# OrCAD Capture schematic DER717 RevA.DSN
size Custom; title: DER 717; rev: A
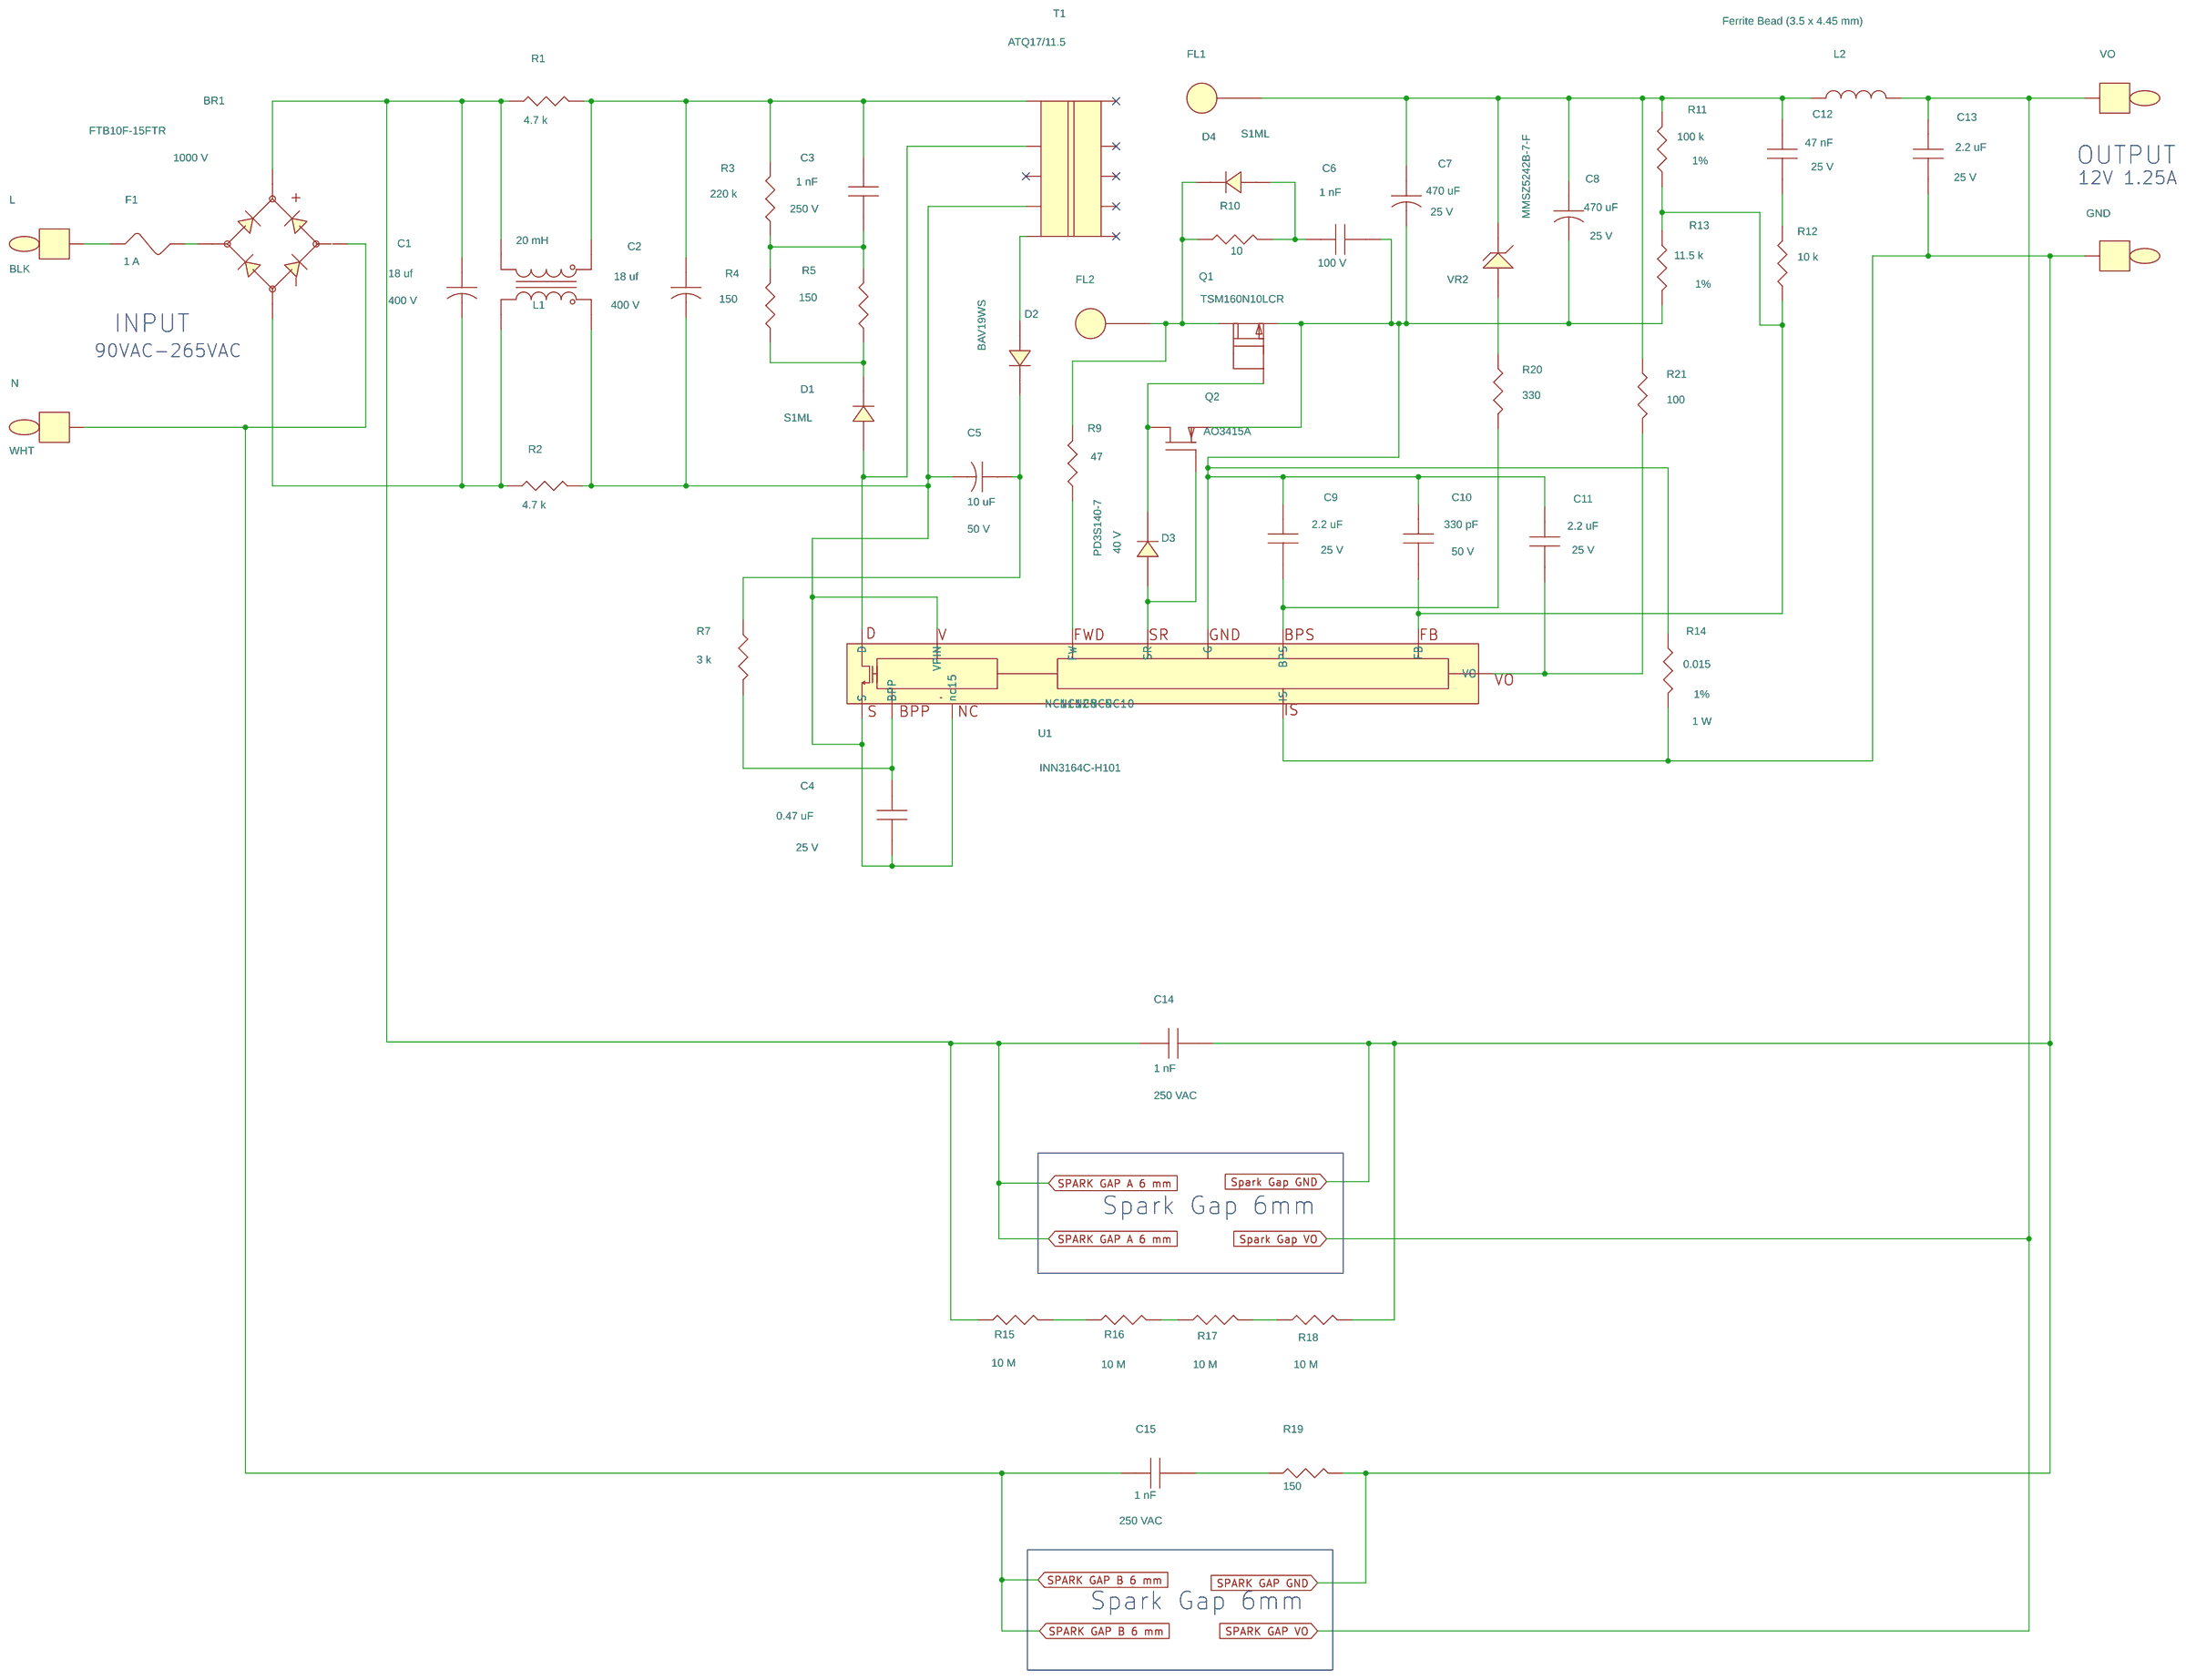
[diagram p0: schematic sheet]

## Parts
BR1  FTB10F-15FTR  [pismd_4SMD]
C1  18 uf  [pipolcapcyld400ls200040]
C2  18 uf  [pipolcapcyld400ls200040]
C3  1 nF  [pismc0805]
C4  0.47 uF  [pismc0805]
C5  10 uF  [pipolcap4p0x11p0xls1p5d030]
C6  1 nF  [pismc0603]
C7  470 uF  [pipolcapcyld400ls200040]
C8  470 uF  [pipolcapcyld400ls200040]
C9  2.2 uF  [pismc0805]
C10  330 pF  [pismc0603]
C11  2.2 uF  [pismc0805]
C12  47 nF  [pismc0603]
C13  2.2 uF  [pismc0805]
C14  1 nF  [pinpycaprad540x290ls400040]
C15  1 nF  [pinpycaprad540x290ls400040]
D1  S1ML  [pi_sm_sod-123_12]
D2  BAV19WS  [pismsod323]
D3  PD3S140-7  [pismd_powerdi323]
D4  S1ML  [pi_sm_sod-123_12]
F1  1 A  [pi_rst_microfuse]
FL1  Hole_50mils  [pi_hole_50mil]
FL2  Hole_50mils  [pi_hole_50mil]
GND  BLK  [pitpkeystone100x100]
L  BLK  [pitpkeystone125x125]
L1  20 mH  [pi_ind_4p_590x295ls394x177d060]
L2  Ferrite Bead (3.5 x 4.45 mm)  [pi12wresd180ls675d040]
N  WHT  [pitpkeystone125x125]
Q1  TSM160N10LCR  [pismpqfn5x6b]
Q2  AO3415A  [pismsot23123_1]
R1  4.7 k  [pismr0805]
R2  4.7 k  [pismr0805]
R3  220 k  [pismr1206]
R4  150  [pismr1206]
R5  150  [pismr1206]
R7  3 k  [pismr0805]
R9  47  [pismr0603]
R10  10  [pismr0805]
R11  100 k  [pismr0603]
R12  10 k  [pismr0603]
R13  11.5 k  [pismr0603]
R14  0.015  [pismr1206]
R15  10 M  [pismr1206]
R16  10 M  [pismr1206]
R17  10 M  [pismr1206]
R18  10 M  [pismr1206]
R19  150  [pismr1206]
R20  330  [pismr0603]
R21  100  [pismr0805]
T1  ATQ17/11.5  [pi_bobbin_ATQ17_H_10P]
U1  INN3164C-H101  [pi_ic_insop_24d]
VO  RED  [pitpkeystone100x100]
VR2  MMSZ5242B-7-F  [pi_sm_sod-123_12]

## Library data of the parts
BR1 = DIODE_BRIDGE_+-~~: Disp_Voltage: 1000 V; Part Number: 15-01264-00
C1 C2 = CAP_POL: ALT_SYMBOLS: pipolcapclyd395x630ls200030h; Disp_Voltage: 400 V; FPLIST: pipolcapcyld400ls200040,pipolcapclyd395x630ls200030h; Part Number: 20-09063-00; Voltage: 400 V
C3 = CAP_NP: Disp_Voltage: 250 V; Part Number: 20-00736-00; Voltage: 250 V
C4 = CAP_NP: Disp_Voltage: 25 V; Part Number: 20-09182-00; Voltage: 25 V
C5 = CAP_POL: Disp_Voltage: 50 V; Part Number: 20-09040-00; Voltage: 50 V
C6 = CAP_NP: Disp_Voltage: 100 V; Part Number: 20-00712-00; Voltage: 100 V
C7 C8 = CAP_POL: ALT_SYMBOLS: pipolcapclyd395x630ls200030h; Disp_Voltage: 25 V; FPLIST: pipolcapcyld400ls200040,pipolcapclyd395x630ls200030h; Part Number: 20-00032-00; Voltage: 25 V
C9 C11 C13 = CAP_NP: Disp_Voltage: 25 V; Part Number: 20-08603-00; Voltage: 25 V
C10 = CAP_NP: ALT_SYMBOLS: pismc0603_1; Disp_Voltage: 50 V; FPLIST: pismc0603,pismc0603_1; Part Number: 20-09235-00; Voltage: 50 V
C12 = CAP_NP: Disp_Voltage: 25 V; Part Number: 20-08756-00; Voltage: 25 V
C14 C15 = CAP_NP: ALT_SYMBOLS: pinpycaprad540x290ls400040h,pinpycaprad500x220ls400040; Disp_Voltage: 250 VAC; FPLIST: pinpycaprad540x290ls400040,pinpycaprad540x290ls400040h,pinpycaprad500x220ls400040; Part Number: 20-00375-00; Voltage: 250 VAC
D1 D4 = DIODE: Part Number: 15-01027-00
D2 = DIODE: Part Number: 15-00658-00
D3 = DIODE: Disp_Voltage: 40 V; Part Number: 15-01025-00
F1 = FUSE: ALT_SYMBOLS: pirstmicrofusehoz; FPLIST: pi_rst_microfuse,pirstmicrofusehoz; Part Number: 40-00053-00
FL1 FL2 = FlyingLead: Part Number: 35-00283-00
GND = TESTPOINT: Part Number: 35-00079-00
L = TESTPOINT: Part Number: 35-00042-00
L1 = INDUCTOR_4P_revD: Part Number: 30-00458-00
L2 = INDUCTOR: ALT_SYMBOLS: pi12wvresd180ls150d040,pi12wvresd180ls200d040,pi12wvresd180ls250d040; FPLIST: pi12wresd180ls675d040,pi12wvresd180ls150d040,pi12wvresd180ls200d040,pi12wvresd180ls250d040; Part Number: 30-00143-00
N = TESTPOINT: Part Number: 35-00044-00
Q1 = FET_N_SGD_123_4_5678: Part Number: 50-00280-00
Q2 = FET_P_GSD: Part Number: 50-00292-00
R1 R2 = R: Part Number: 05-01535-00
R3 = R: Part Number: 05-01408-00
R4 R5 R19 = R: ALT_SYMBOLS: pismr1206_1; FPLIST: pismr1206,pismr1206_1; Part Number: 05-01332-00
R7 = R: Part Number: 05-01530-00
R9 = R: ALT_SYMBOLS: pismr0603_1; FPLIST: pismr0603,pismr0603_1; Part Number: 05-01656-00
R10 = R: Part Number: 05-01471-00
R11 = R: Disp_Tol: 1%; Part Number: 05-01174-00
R12 = R: Part Number: 05-01712-00
R13 = R: Disp_Tol: 1%; Part Number: 05-03188-00
R14 = R: Disp_Power: 1 W; Disp_Tol: 1%; Part Number: 05-06450-00
R15-R18 = R: Part Number: 05-01445-00
R20 = R: Part Number: 05-01676-00
R21 = R: Part Number: 05-01495-00
T1 = BATQ17_10P_GENERIC: Part Number: 25-01175-00
U1 = Inno3CE_P15: Part Number: 10-01031-00
VO = TESTPOINT: Part Number: 35-00080-00
VR2 = DIODE_ZENER: Part Number: 15-01090-00

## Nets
NC8: U1.8(NC8)
NC9: U1.9(NC9)
NC10: U1.10(NC10)
NC11: U1.11(NC11)
NC12: U1.12(NC12)
SPARK GAP A 6 mm: BR1.1 C1.1 C14.1 L1.2 R1.1 R15.1
SPARK GAP B 6 mm: BR1.3 C15.1 N.1
SPARK GAP GND: C13.2 C14.2 GND.1 R14.2 R18.2 R19.2 U1.1(IS)
SPARK GAP VO: C13.1 L2.2 VO.1
N05007: BR1.2 C1.2 L1.3 R2.1
N05208: C2.1 C3.1 L1.1 R1.2 R3.1 T1.1
N05228: C2.2 C4.2 C5.2 L1.4 R2.2 T1.4 U1.13(VPIN) U1.15(nc15) U1.16(S)
N06587: C3.2 R3.2 R4.1 R5.1
N06642: D1.1 R4.2 R5.2
N06679: D1.2 T1.2 U1.24(D)
N06800: C4.1 R7.2 U1.14(BPP)
N06937: D2.2 T1.5
N06978: C5.1 D2.1 R7.1
N12310296: R9.2 U1.7(FW)
N12310343: D3.2 Q2.1(G) U1.5(SR)
N12310347: D3.1 Q1.4(G) Q2.2(S)
N12310367: D4.1 FL2.1 Q1.5(D) R9.1 R10.1
N12310400: C6.2 C7.2 C8.2 C9.1 C10.1 C11.1 Q1.1(S) Q2.3(D) R13.2 R14.1 U1.2(G)
N12325405: C6.1 D4.2 R10.2
N12325650: C7.1 C8.1 C12.1 FL1.1 L2.1 R11.1 R21.2 VR2.1
N12325783: C9.2 R20.1 U1.4(BPS)
N12326606: C10.2 R11.2 R12.2 R13.1 U1.3(FB)
N12326726: C11.2 R21.1 U1.6(VO)
N12328885: R15.2 R16.1
N12328893: R16.2 R17.1
N12328897: R17.2 R18.1
N12330008: R20.2 VR2.2
N12331495: BR1.4 F1.2
N12339011: C15.2 R19.1
N12348785: F1.1 L.1
N12358873: C12.2 R12.1

Not connected (* = marked no-connect by the designer): Q1 2(S2) 3(S3) 6(D6) 7(D7) 8(D8); T1 3* 6* 7* 8* 9* 10*

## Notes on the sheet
- OUTPUT
- 12V 1.25A
- INPUT
- 90VAC-265VAC
- Spark Gap 6mm
- Spark Gap 6mm
